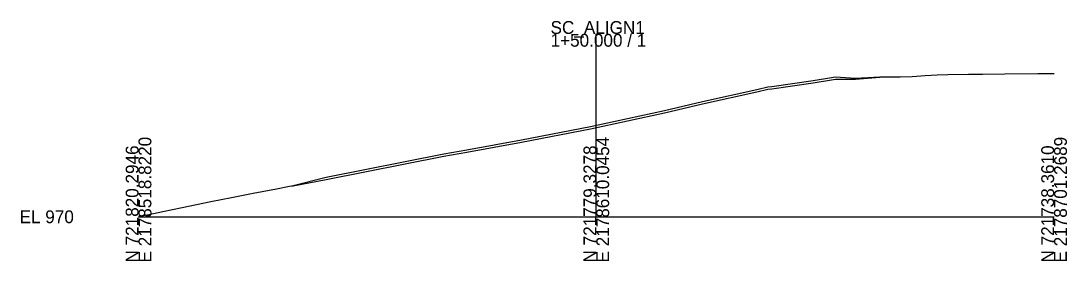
# Model space of a CAD drawing. Extents: x -2342 to 14913, y -10 to 5257.
# Drawn here: x -25.7 to 202.8, y 2990.3 to 3042.8 of the extents above; entities that cross this region are included whole.
import ezdxf

# ---------------------------------------------------------------- set-up
doc = ezdxf.new("R2010")
doc.units = 0
for name, color, linetype in [('Default', 7, 'Continuous'), ('GK_Cells', 7, 'Continuous'), ('SC_Scratch1', 7, 'Continuous'), ('XS_X_Ground_Line', 7, 'Continuous')]:
    doc.layers.add(name, color=color, linetype=linetype)

msp = doc.modelspace()

# ---------------------------------------------------------------- linework, layer by layer
at = {"layer": 'GK_Cells'}
for p, q in [((100, 3000), (100, 3040)), ((0, 3000), (100, 3000)), ((100, 3000), (200, 3000))]:
    msp.add_line(p, q, dxfattribs=at)
at = {"layer": 'SC_Scratch1'}
msp.add_lwpolyline([(0, 3000.15), (2.25, 3000.53), (5.29, 3001.16), (9.53, 3002.03), (15.81, 3003.36), (20.3, 3004.23), (25.02, 3005.13), (30.12, 3006.1), (33.01, 3006.67), (33.75, 3006.8), (40.97, 3008.14), (66.66, 3013.27), (71.74, 3014.16), (83.64, 3016.32), (98.76, 3019.25), (114.89, 3022.74), (123.2, 3024.7), (135.06, 3027.35), (137.5, 3027.89), (138.31, 3028), (147.39, 3029.29), (151.38, 3029.94), (152.26, 3030.13), (156.65, 3030.11), (161.93, 3030.51), (166.41, 3030.64), (168.98, 3030.69), (171.82, 3030.9), (174.46, 3031.04), (176.78, 3031.13), (181.32, 3031.22), (184.37, 3031.17), (189.21, 3031.24), (196.46, 3031.34), (196.91, 3031.36), (197.49, 3031.36), (200, 3031.37)], dxfattribs=at)
at = {"layer": 'XS_X_Ground_Line'}
msp.add_lwpolyline([(0, 3000.15), (2.25, 3000.53), (5.29, 3001.16), (9.53, 3002.03), (15.81, 3003.36), (20.3, 3004.23), (25.02, 3005.13), (30.12, 3006.1), (33.01, 3006.67), (33.75, 3006.83), (40.97, 3008.65), (66.66, 3013.78), (71.74, 3014.67), (83.64, 3016.83), (98.76, 3019.76), (114.89, 3023.25), (123.2, 3025.21), (135.06, 3027.86), (137.5, 3028.39), (138.31, 3028.51), (147.39, 3029.8), (151.38, 3030.45), (152.26, 3030.64), (156.65, 3030.3), (161.93, 3030.59), (166.41, 3030.64), (168.98, 3030.69), (171.82, 3030.9), (174.46, 3031.04), (176.78, 3031.13), (181.32, 3031.22), (184.37, 3031.17), (189.21, 3031.24), (196.46, 3031.34), (196.91, 3031.36), (197.49, 3031.36), (200, 3031.37)], dxfattribs=at)

# ---------------------------------------------------------------- texts
at = {"layer": 'Default'}
msp.add_text('-', height=0.0001, dxfattribs=at).set_placement((0, 3000))
at = {"layer": 'GK_Cells'}
for s, p in [('SC_ALIGN1', (90, 3040)), ('1+50.000 / 1', (90, 3037.2)), ('EL 970', (-26, 2998.6))]:
    msp.add_text(s, height=2.8, dxfattribs=at).set_placement(p)
for s, p in [('E 2178518.8220', (2.8, 2990)), ('E 2178610.0454', (102.8, 2990)), ('E 2178701.2689', (202.8, 2990)), ('N 721820.2946', (0, 2990)), ('N 721779.3278', (100, 2990)), ('N 721738.3610', (200, 2990))]:
    msp.add_text(s, height=2.8, rotation=90, dxfattribs=at).set_placement(p)
at = {"layer": 'SC_Scratch1'}
msp.add_text('X', height=0.0001, dxfattribs=at).set_placement((100, 3020.03))

doc.saveas('drawing.dxf')
